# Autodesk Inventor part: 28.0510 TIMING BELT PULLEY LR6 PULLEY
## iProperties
Created: 2007-06
Part Number: 28.0510 TIMING BELT PULLEY LR6 PULLEY
Document SubType Name: Modeling
Designer: Andy Moles
Material: Aluminum-6061
Density: 2.71 g/cm^3
Author: Andy Moles
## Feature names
1. Revolution1
2. Extrusion1
3. Circular Pattern1
4. Extrusion2
5. Mirror1
